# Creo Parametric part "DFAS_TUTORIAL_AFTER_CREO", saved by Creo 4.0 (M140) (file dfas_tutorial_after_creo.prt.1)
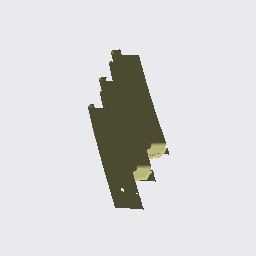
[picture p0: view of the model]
Units: ely_unitsystem; MM, GRAM, SECS

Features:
  1. coordinate system "CS0"
  2. imported feature
  3. imported feature
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
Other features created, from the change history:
  coordinate system "CS1"

Other named items: AXIS61_1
